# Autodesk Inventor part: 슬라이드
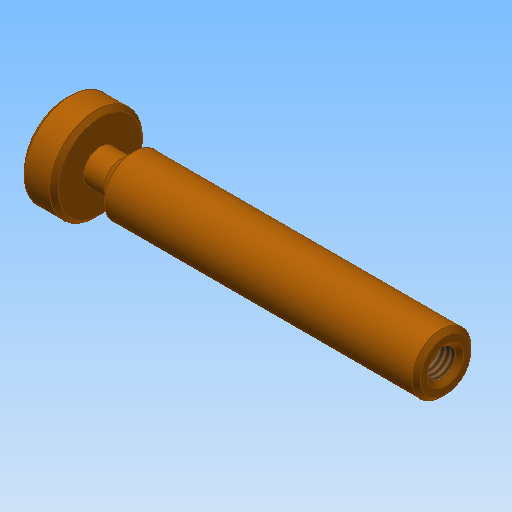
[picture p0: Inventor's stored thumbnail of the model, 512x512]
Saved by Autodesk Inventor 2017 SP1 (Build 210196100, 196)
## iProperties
Created: 2015-12
Part Number: 슬라이드
Document SubType Name: Modeling
Designer: mdu
Density: 8.08 g/cm^3
Material: 스테인리스강
Mass: 116.651 g
Surface Area: 50.7862 cm^2
Volume: 14.437 cm^3
Appearance: 주황색
Author: mdu
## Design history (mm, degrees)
sketch "스케치1"
  geometry: L1 (-45, 0)-(45, 0); L2 (-45, 0)-(-45, 11); L3 (-45, 11)-(-37, 11); L4 (-37, 11)-(-37, 4); L5 (-37, 4)-(-32, 4); L6 (-32, 4)-(-29, 7); L7 (-29, 7)-(45, 7); L8 (45, 7)-(45, 0); 2 further points
  constraints: 16 end point, 4 parallel, 2 perpendicular, 1 coincident, 1 horizontal, 1 midpoint
  dimensions: "d0" = 90 distance of L1.start L1.end; "d1" = 22 diameter of L3 L1; "d2" = 14 diameter of L7 L1; "d3" = 8 diameter of L5 L1; "d4" = 8 distance of L2.end L3.end; "d5" = 5 distance of L4.end L5.end; "d6" = 135 deg angle of L6 L5
revolve "회전1" sketch "스케치1" stored, may be unused: angle "d7" = 90 deg
chamfer "모따기1" distance "d8" = 1; stored, may be unused: second distance "d9" = 2, angle "d10" = 45 deg
hole "구멍1" diameter "d13" = 6.647; stored, may be unused: countersink angle "d17" = 90 deg, drill point angle "d19" = 118 deg; dims "d11" = 10, "d12" = 10, "d14" = 9, "d15" = 4, "d16" = 2, "d18" = 12
chamfer "모따기2" distance "d20" = 1; stored, may be unused: second distance "d21" = 2, angle "d22" = 45 deg
node "솔리드1"
